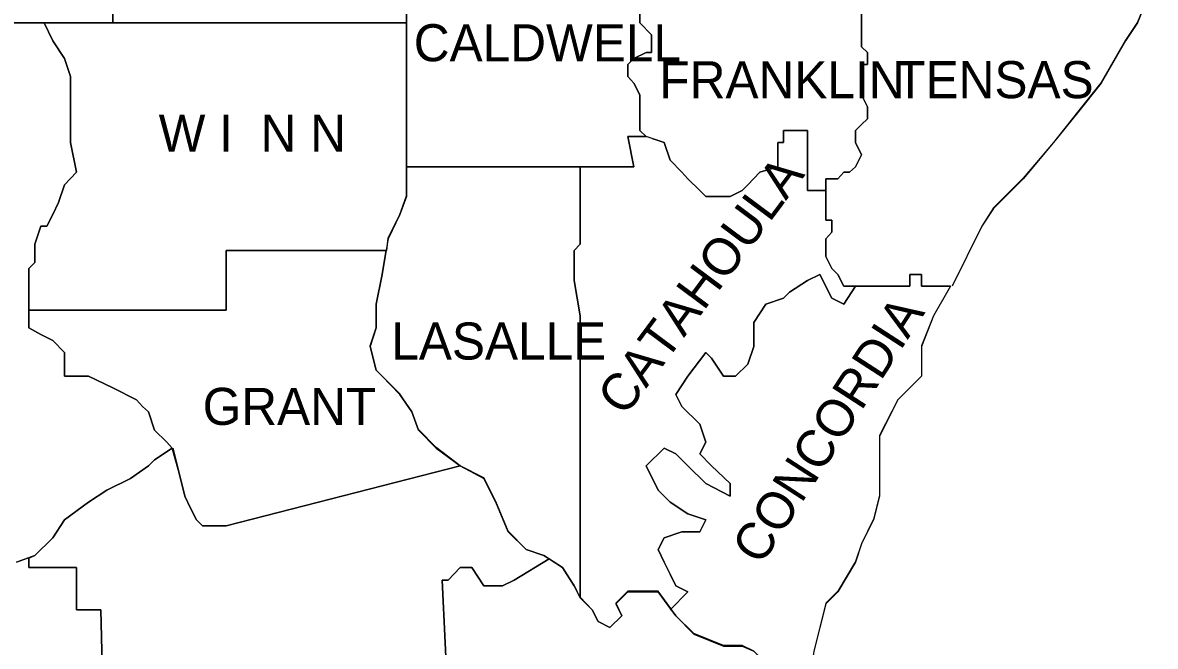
# Model space of a CAD drawing. Extents: x 0.19 to 2.82, y 0.04 to 1.79.
# Drawn here: x 2.2917 to 2.4347, y 1.594 to 1.6727 of the extents above; entities that cross this region are included whole.
import ezdxf

# ---------------------------------------------------------------- set-up
doc = ezdxf.new("R2010")
doc.units = 0
for name, color, linetype in [('Dist08', 7, 'Continuous'), ('Dist58', 7, 'Continuous'), ('Standard Info', 7, 'Continuous')]:
    doc.layers.add(name, color=color, linetype=linetype)

msp = doc.modelspace()

# ---------------------------------------------------------------- linework, layer by layer
at = {"layer": 'Dist08'}
for points in [[(2.34015, 1.65458), (2.34015, 1.67275)], [(2.33765, 1.644), (2.33782, 1.6455), (2.33932, 1.6485), (2.34015, 1.65083), (2.34015, 1.65458)], [(2.36207, 1.60008), (2.36132, 1.60167), (2.35982, 1.60392), (2.35749, 1.60542), (2.35524, 1.60617), (2.35299, 1.6085), (2.3514, 1.61225), (2.3499, 1.61525), (2.3469, 1.61675), (2.3439, 1.61908), (2.34165, 1.62133), (2.34082, 1.62358), (2.33932, 1.62583), (2.33707, 1.62808), (2.33632, 1.62883), (2.33557, 1.63192), (2.33632, 1.63417), (2.33632, 1.63717), (2.33707, 1.64092), (2.33757, 1.644)], [(2.37349, 1.59875), (2.3719, 1.60092), (2.36807, 1.60092), (2.36657, 1.59942), (2.36732, 1.59783), (2.36582, 1.59633), (2.36432, 1.59708), (2.36357, 1.59858), (2.36207, 1.60017)], [(2.38057, 1.57817), (2.38249, 1.582), (2.38399, 1.5835), (2.38399, 1.5865), (2.38474, 1.5895), (2.38549, 1.59183), (2.38399, 1.59333), (2.38249, 1.59408), (2.38015, 1.59408), (2.3764, 1.59558), (2.37415, 1.59783), (2.37349, 1.59875)]]:
    msp.add_lwpolyline(points, dxfattribs=at)
at = {"layer": 'Dist58'}
for points in [[(2.43465, 1.67875), (2.4339, 1.6765), (2.4324, 1.67275), (2.4309, 1.6705), (2.42782, 1.66517), (2.42482, 1.66142), (2.42182, 1.65758), (2.41799, 1.65308), (2.41424, 1.64933), (2.41274, 1.647), (2.40899, 1.63942)], [(2.34015, 1.65458), (2.34015, 1.67275)], [(2.33765, 1.644), (2.33782, 1.6455), (2.33932, 1.6485), (2.34015, 1.65083), (2.34015, 1.65458)], [(2.36207, 1.60008), (2.36132, 1.60167), (2.35982, 1.60392), (2.35749, 1.60542), (2.35524, 1.60617), (2.35299, 1.6085), (2.3514, 1.61225), (2.3499, 1.61525), (2.3469, 1.61675), (2.3439, 1.61908), (2.34165, 1.62133), (2.34082, 1.62358), (2.33932, 1.62583), (2.33707, 1.62808), (2.33632, 1.62883), (2.33557, 1.63192), (2.33632, 1.63417), (2.33632, 1.63717), (2.33707, 1.64092), (2.33757, 1.644)], [(2.40882, 1.63942), (2.40665, 1.63567), (2.40515, 1.63192), (2.40515, 1.62808), (2.40215, 1.62508), (2.39982, 1.62058), (2.39982, 1.613), (2.39907, 1.61), (2.39757, 1.60692), (2.39682, 1.60467), (2.39457, 1.60092), (2.39307, 1.59942), (2.39157, 1.59333), (2.39074, 1.588), (2.39157, 1.58425), (2.39232, 1.58275), (2.39382, 1.57975)], [(2.37349, 1.59875), (2.3719, 1.60092), (2.36807, 1.60092), (2.36657, 1.59942), (2.36732, 1.59783), (2.36582, 1.59633), (2.36432, 1.59708), (2.36357, 1.59858), (2.36207, 1.60017)], [(2.38057, 1.57817), (2.38249, 1.582), (2.38399, 1.5835), (2.38399, 1.5865), (2.38474, 1.5895), (2.38549, 1.59183), (2.38399, 1.59333), (2.38249, 1.59408), (2.38015, 1.59408), (2.3764, 1.59558), (2.37415, 1.59783), (2.37349, 1.59875)]]:
    msp.add_lwpolyline(points, dxfattribs=at)
at = {"layer": 'Standard Info'}
for p, q in [((2.33774, 1.645), (2.33757, 1.64392)), ((2.2909, 1.60458), (2.29249, 1.60517)), ((2.29249, 1.60517), (2.29265, 1.60517))]:
    msp.add_line(p, q, dxfattribs=at)
for points in [[(2.30682, 1.6985), (2.30682, 1.67958), (2.3054, 1.67875), (2.3054, 1.6765), (2.3054, 1.67575), (2.3039, 1.67575), (2.30307, 1.675), (2.30307, 1.67267)], [(2.30307, 1.67267), (2.30307, 1.675), (2.30382, 1.67567), (2.30532, 1.67567), (2.30532, 1.6765), (2.30532, 1.67875), (2.30682, 1.6795), (2.30682, 1.69842)], [(2.34015, 1.68392), (2.34015, 1.67267)], [(2.34015, 1.67267), (2.34015, 1.68383)], [(2.43465, 1.67875), (2.4339, 1.6765), (2.4324, 1.67267), (2.4309, 1.67042), (2.42782, 1.66508), (2.42482, 1.66133), (2.42182, 1.65758), (2.41799, 1.653), (2.41424, 1.64925), (2.41274, 1.647), (2.40899, 1.63942)], [(2.39832, 1.678), (2.39832, 1.67417), (2.39757, 1.67417), (2.39757, 1.66967), (2.39832, 1.66892), (2.39832, 1.66742), (2.39757, 1.66742), (2.39757, 1.66358), (2.39832, 1.66208), (2.39832, 1.66058), (2.39757, 1.65983), (2.39682, 1.65908), (2.39682, 1.65758), (2.39757, 1.656), (2.39682, 1.6545), (2.39607, 1.65383), (2.39532, 1.65383), (2.39457, 1.653), (2.39307, 1.653), (2.39307, 1.6515)], [(2.36957, 1.675), (2.36957, 1.67267), (2.37107, 1.67117), (2.37107, 1.66892), (2.3704, 1.66892), (2.36882, 1.66817), (2.36807, 1.66742), (2.36807, 1.66592), (2.36882, 1.66508), (2.36957, 1.66358), (2.36957, 1.66133), (2.36957, 1.65908), (2.3704, 1.65833)], [(2.39307, 1.6515), (2.39074, 1.6515), (2.39074, 1.65908), (2.38774, 1.65908), (2.38774, 1.65758), (2.38699, 1.65758), (2.38699, 1.656), (2.38699, 1.6545), (2.38474, 1.65383), (2.38324, 1.65225), (2.38249, 1.6515), (2.38099, 1.65075), (2.37949, 1.65075), (2.3779, 1.65075), (2.37715, 1.6515), (2.37565, 1.653), (2.3749, 1.65383), (2.3734, 1.65533), (2.37265, 1.65758), (2.3704, 1.65833), (2.36957, 1.65908), (2.36957, 1.66133), (2.36957, 1.66358), (2.36882, 1.66508), (2.36807, 1.66592), (2.36807, 1.66742), (2.36882, 1.66817), (2.3704, 1.66892), (2.37107, 1.66892), (2.37107, 1.67117), (2.36957, 1.67267), (2.36957, 1.675)], [(2.40882, 1.63942), (2.40515, 1.63942), (2.40515, 1.64092), (2.40365, 1.64092), (2.40365, 1.63942), (2.40215, 1.63942), (2.39757, 1.63942), (2.39532, 1.63942), (2.39457, 1.64092), (2.39382, 1.64167), (2.39307, 1.64317), (2.39307, 1.64392), (2.39307, 1.64542), (2.39382, 1.64625), (2.39382, 1.64775), (2.39307, 1.64775), (2.39307, 1.653), (2.39457, 1.653), (2.39532, 1.65383), (2.39607, 1.65383), (2.39682, 1.6545), (2.39757, 1.656), (2.39682, 1.65758), (2.39682, 1.65908), (2.39757, 1.65983), (2.39832, 1.66058), (2.39832, 1.66208), (2.39757, 1.66358), (2.39757, 1.66742), (2.39832, 1.66742), (2.39832, 1.66892), (2.39757, 1.66967), (2.39757, 1.67417)], [(2.27657, 1.67267), (2.2944, 1.67267)], [(2.30307, 1.67267), (2.27665, 1.67267)], [(2.29249, 1.63642), (2.29249, 1.64167), (2.29324, 1.64242), (2.29324, 1.64317), (2.29324, 1.64475), (2.29399, 1.647), (2.29474, 1.647), (2.29549, 1.6485), (2.29624, 1.65), (2.29699, 1.65225), (2.29849, 1.65383), (2.29774, 1.65758), (2.29774, 1.66133), (2.29774, 1.66358), (2.29774, 1.66592), (2.29699, 1.66817), (2.29549, 1.67042), (2.2944, 1.67267)], [(2.2944, 1.67267), (2.29549, 1.67042), (2.29699, 1.66817), (2.29774, 1.66592), (2.29774, 1.66358), (2.29774, 1.66133), (2.29774, 1.65758), (2.29849, 1.65383), (2.29699, 1.65225), (2.29624, 1.65), (2.29549, 1.6485), (2.29474, 1.647), (2.29399, 1.647), (2.29324, 1.64475), (2.29324, 1.64317), (2.29324, 1.64242), (2.29249, 1.64167), (2.29249, 1.63417), (2.29399, 1.63333), (2.29549, 1.63258), (2.29699, 1.63108), (2.29699, 1.63033), (2.29699, 1.62808), (2.29999, 1.62808), (2.30307, 1.62658), (2.30607, 1.62508), (2.30682, 1.62425), (2.30757, 1.62358), (2.30832, 1.62125), (2.3099, 1.61975), (2.31057, 1.619)], [(2.2944, 1.67267), (2.34015, 1.67267)], [(2.34015, 1.67267), (2.30307, 1.67267)], [(2.34015, 1.67267), (2.34015, 1.65075), (2.33932, 1.6485), (2.33782, 1.64542), (2.33774, 1.645)], [(2.34015, 1.6545), (2.34015, 1.67267)], [(2.3704, 1.65833), (2.36807, 1.65833), (2.36882, 1.6545), (2.36207, 1.6545), (2.34015, 1.6545)], [(2.36207, 1.6545), (2.36882, 1.6545), (2.36807, 1.65833), (2.3704, 1.65833)], [(2.37115, 1.65808), (2.37265, 1.65758), (2.3734, 1.65533), (2.3749, 1.65383), (2.37565, 1.653), (2.37715, 1.6515), (2.3779, 1.65075), (2.37949, 1.65075), (2.38099, 1.65075), (2.38249, 1.6515), (2.38324, 1.65225), (2.38474, 1.65383), (2.38699, 1.6545), (2.38699, 1.656), (2.38699, 1.65758), (2.38774, 1.65758), (2.38774, 1.65908), (2.39074, 1.65908), (2.39074, 1.6515), (2.39307, 1.6515)], [(2.33765, 1.64392), (2.33782, 1.64542), (2.33932, 1.6485), (2.34015, 1.65075), (2.34015, 1.6545)], [(2.34015, 1.6545), (2.36207, 1.6545)], [(2.36207, 1.6545), (2.36207, 1.64475), (2.36132, 1.64392), (2.36132, 1.64017), (2.36207, 1.63567), (2.36207, 1.60008)], [(2.36207, 1.60008), (2.36207, 1.63567), (2.36132, 1.64017), (2.36132, 1.64392), (2.36207, 1.64475), (2.36207, 1.6545)], [(2.39307, 1.6515), (2.39307, 1.64775), (2.39382, 1.64775), (2.39382, 1.64625), (2.39307, 1.64542), (2.39307, 1.64392), (2.39307, 1.64317), (2.39382, 1.64167), (2.39457, 1.64092), (2.39532, 1.63942), (2.39682, 1.63942)], [(2.33757, 1.64392), (2.3174, 1.64392), (2.3174, 1.63642), (2.29699, 1.63642), (2.29249, 1.63642)], [(2.29249, 1.63642), (2.29699, 1.63642), (2.3174, 1.63642), (2.3174, 1.64392), (2.33757, 1.64392)], [(2.36207, 1.60008), (2.36132, 1.60158), (2.35982, 1.60392), (2.35749, 1.60542), (2.35524, 1.60617), (2.35299, 1.60842), (2.3514, 1.61217), (2.3499, 1.61517), (2.3469, 1.61675), (2.3439, 1.619), (2.34165, 1.62125), (2.34082, 1.62358), (2.33932, 1.62575), (2.33707, 1.62808), (2.33632, 1.62883), (2.33557, 1.63183), (2.33632, 1.63417), (2.33632, 1.63717), (2.33707, 1.64092), (2.33757, 1.64392)], [(2.33757, 1.64392), (2.33707, 1.64092), (2.33632, 1.63717), (2.33632, 1.63417), (2.33557, 1.63183), (2.33632, 1.62883), (2.33707, 1.62808), (2.33932, 1.62575), (2.34082, 1.62358), (2.34165, 1.62125), (2.3439, 1.619), (2.3469, 1.61675)], [(2.39682, 1.63942), (2.39532, 1.63717), (2.39382, 1.63792), (2.39232, 1.64092), (2.39074, 1.64017), (2.38849, 1.63867), (2.38774, 1.63792), (2.38549, 1.63717), (2.38399, 1.63483), (2.38399, 1.63333), (2.38399, 1.63183), (2.38324, 1.62958), (2.38165, 1.62808), (2.38015, 1.62808), (2.37865, 1.63033), (2.3779, 1.63108), (2.37565, 1.62808), (2.37415, 1.62575), (2.3749, 1.62425), (2.37715, 1.622), (2.3779, 1.61975), (2.37715, 1.61825), (2.37865, 1.61675), (2.38099, 1.6145), (2.38099, 1.61292), (2.3779, 1.6145), (2.37565, 1.61675), (2.37415, 1.61825), (2.37265, 1.619), (2.3704, 1.61675), (2.3719, 1.61367), (2.3734, 1.61217), (2.37565, 1.61067), (2.3779, 1.60992), (2.37715, 1.60842), (2.3749, 1.60842), (2.37265, 1.60767), (2.3719, 1.60617), (2.37265, 1.60458), (2.3734, 1.60308), (2.37415, 1.60158), (2.37565, 1.60083), (2.3734, 1.59858)], [(2.3734, 1.59858), (2.37565, 1.60083), (2.37415, 1.60158), (2.3734, 1.60308), (2.37265, 1.60458), (2.3719, 1.60617), (2.37265, 1.60767), (2.3749, 1.60842), (2.37715, 1.60842), (2.3779, 1.60992), (2.37565, 1.61067), (2.3734, 1.61217), (2.3719, 1.61367), (2.3704, 1.61675), (2.37265, 1.619), (2.37415, 1.61825), (2.37565, 1.61675), (2.3779, 1.6145), (2.38099, 1.61292), (2.38099, 1.6145), (2.37865, 1.61675), (2.37715, 1.61825), (2.3779, 1.61975), (2.37715, 1.622), (2.3749, 1.62425), (2.37415, 1.62575), (2.37565, 1.62808), (2.3779, 1.63108), (2.37865, 1.63033), (2.38015, 1.62808), (2.38165, 1.62808), (2.38324, 1.62958), (2.38399, 1.63183), (2.38399, 1.63333), (2.38399, 1.63483), (2.38549, 1.63717), (2.38774, 1.63792), (2.38849, 1.63867), (2.39074, 1.64017), (2.39232, 1.64092), (2.39382, 1.63792), (2.39532, 1.63717), (2.39682, 1.63942)], [(2.39682, 1.63942), (2.40215, 1.63942), (2.40365, 1.63942), (2.40365, 1.64092), (2.40515, 1.64092), (2.40515, 1.63942), (2.40882, 1.63942)], [(2.40882, 1.63942), (2.40665, 1.63567), (2.40515, 1.63183), (2.40515, 1.62808), (2.40215, 1.62508), (2.39982, 1.6205), (2.39982, 1.61292), (2.39907, 1.60992), (2.39757, 1.60692), (2.39682, 1.60458), (2.39457, 1.60083), (2.39307, 1.59933), (2.39157, 1.59333), (2.39074, 1.588), (2.39157, 1.58425), (2.39232, 1.58267), (2.39382, 1.57967)], [(2.3469, 1.61675), (2.3174, 1.60917), (2.3144, 1.60917), (2.31365, 1.60992), (2.3129, 1.61142), (2.31215, 1.61292), (2.3114, 1.616), (2.31057, 1.619), (2.3099, 1.61975), (2.30832, 1.62125), (2.30757, 1.62358), (2.30682, 1.62425), (2.30607, 1.62508), (2.30307, 1.62658), (2.29999, 1.62808), (2.29699, 1.62808), (2.29699, 1.63033), (2.29699, 1.63108), (2.29549, 1.63258), (2.29399, 1.63333), (2.29249, 1.63417), (2.29249, 1.63642)], [(2.31057, 1.619), (2.30832, 1.6175), (2.30757, 1.61675), (2.30532, 1.61517), (2.30232, 1.61367), (2.29999, 1.61217), (2.29699, 1.60992), (2.29549, 1.60767), (2.29324, 1.60542), (2.2909, 1.60458)], [(2.2909, 1.60458), (2.29324, 1.60542), (2.29549, 1.60767), (2.29699, 1.60992), (2.29999, 1.61217), (2.30232, 1.61367), (2.30532, 1.61517), (2.30757, 1.61675), (2.30832, 1.6175), (2.31057, 1.619)], [(2.29265, 1.60517), (2.29324, 1.60542), (2.29549, 1.60767), (2.29699, 1.60992), (2.29999, 1.61217), (2.30232, 1.61367), (2.30532, 1.61517), (2.30757, 1.61675), (2.30832, 1.6175), (2.31057, 1.619)], [(2.31065, 1.619), (2.3114, 1.616), (2.31215, 1.61292), (2.3129, 1.61142), (2.31365, 1.60992), (2.3144, 1.60917), (2.3174, 1.60917), (2.3469, 1.61675)], [(2.3469, 1.61675), (2.3499, 1.61517), (2.3514, 1.61217), (2.35299, 1.60842), (2.35524, 1.60617), (2.35749, 1.60542), (2.35815, 1.605)], [(2.29249, 1.60517), (2.29249, 1.60392), (2.29849, 1.60392), (2.29849, 1.59858), (2.30157, 1.59858), (2.30232, 1.56758)], [(2.29249, 1.60517), (2.29249, 1.60392), (2.29849, 1.60392), (2.29849, 1.59858), (2.30157, 1.59858), (2.30232, 1.56758)], [(2.30232, 1.56758), (2.30157, 1.59858), (2.29849, 1.59858), (2.29849, 1.60392), (2.29249, 1.60392), (2.29249, 1.60517)], [(2.29249, 1.60508), (2.29249, 1.60392), (2.29849, 1.60392), (2.29849, 1.59858), (2.30157, 1.59858), (2.30232, 1.56758)], [(2.35815, 1.605), (2.35374, 1.60233), (2.35224, 1.60158), (2.35074, 1.60158), (2.3499, 1.60158), (2.3484, 1.60392), (2.3469, 1.60392), (2.3454, 1.60233), (2.34465, 1.60233), (2.3454, 1.5865), (2.34615, 1.57967), (2.3484, 1.57283), (2.3424, 1.57283)], [(2.3424, 1.57283), (2.3484, 1.57283), (2.34615, 1.57967), (2.3454, 1.5865), (2.34465, 1.60233), (2.3454, 1.60233), (2.3469, 1.60392), (2.3484, 1.60392), (2.3499, 1.60158), (2.35074, 1.60158), (2.35224, 1.60158), (2.35374, 1.60233), (2.35815, 1.605)], [(2.35815, 1.605), (2.35982, 1.60392), (2.36132, 1.60158), (2.36207, 1.60008), (2.36357, 1.59858), (2.36432, 1.59708), (2.36582, 1.59633), (2.36732, 1.59783), (2.36657, 1.59933), (2.36807, 1.60083), (2.3719, 1.60083), (2.37415, 1.59783), (2.3764, 1.5955), (2.38015, 1.594), (2.38249, 1.594), (2.38399, 1.59333), (2.38549, 1.59175), (2.38474, 1.5895), (2.38399, 1.5865), (2.38399, 1.58342), (2.38249, 1.58192), (2.38065, 1.57833)], [(2.37349, 1.59867), (2.3719, 1.60083), (2.36807, 1.60083), (2.36657, 1.59933), (2.36732, 1.59783), (2.36582, 1.59633), (2.36432, 1.59708), (2.36357, 1.59858), (2.36207, 1.60017)], [(2.38057, 1.57817), (2.38249, 1.58192), (2.38399, 1.58342), (2.38399, 1.5865), (2.38474, 1.5895), (2.38549, 1.59175), (2.38399, 1.59333), (2.38249, 1.594), (2.38015, 1.594), (2.3764, 1.5955), (2.37415, 1.59783), (2.37349, 1.59867)]]:
    msp.add_lwpolyline(points, dxfattribs=at)

# ---------------------------------------------------------------- texts
for s, p in [('CALDWELL', (2.34106, 1.66783)), ('FRANKLIN', (2.37206, 1.66316)), ('TENSAS', (2.40183, 1.66317)), ('W I  N N', (2.30886, 1.65642)), ('LASALLE', (2.33822, 1.63017)), ('GRANT', (2.31442, 1.62192))]:
    msp.add_text(s, height=0.004679, dxfattribs=at).set_placement(p)
for s, rotation, p in [('CATAHOULA', 53.3344, (2.36768, 1.62284)), ('CONCORDIA', 57.0945, (2.38489, 1.60403))]:
    msp.add_text(s, height=0.004679, rotation=rotation, dxfattribs=at).set_placement(p)

doc.saveas('drawing.dxf')
